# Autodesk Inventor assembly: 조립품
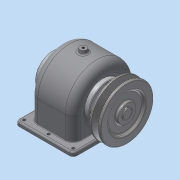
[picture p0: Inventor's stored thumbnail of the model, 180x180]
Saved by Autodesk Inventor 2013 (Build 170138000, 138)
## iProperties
Created: 2015-09
Part Number: 조립품
Document SubType Name: Assembly
Designer: dgall
Author: dgall
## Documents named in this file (14)
- C:\Users\dgall\Desktop\450907V1038\조립품.iam
- C:\Users\dgall\Desktop\450907V1038\본체.ipt
- C:\Users\dgall\Desktop\450907V1038\축.ipt
- C:\Users\dgall\Desktop\450907V1038\키 - 6 x 6 x 22.ipt
- C:\Users\dgall\Desktop\450907V1038\키 - 5 x 5 x 18.ipt
- C:\Users\dgall\Desktop\450907V1038\V-벨트풀리.ipt
- C:\Users\dgall\Desktop\450907V1038\베어링 6203.ipt
- C:\Users\dgall\Desktop\450907V1038\스퍼기어.ipt
- C:\Users\dgall\Desktop\450907V1038\멈춤나사 - M4x10.ipt
- C:\Users\dgall\Desktop\450907V1038\앞커버.ipt
- C:\Users\dgall\Desktop\450907V1038\뒤커버.ipt
- C:\Users\dgall\Desktop\450907V1038\오일 실 17 32 8.ipt
- C:\Users\dgall\Desktop\450907V1038\볼트 M3 x 10.ipt
- C:\Users\dgall\Desktop\450907V1038\볼트 M3 x 8.ipt
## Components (9 placed, 3 different names)
1. V-벨트풀리:1
2. ISO 4762 M3 x 10:1
3. ISO 4762 M3 x 10:2
4. ISO 4762 M3 x 10:3
5. ISO 4762 M3 x 10:4
6. ISO 4762 M3 x 8:1
7. ISO 4762 M3 x 8:2
8. ISO 4762 M3 x 8:3
9. ISO 4762 M3 x 8:4
